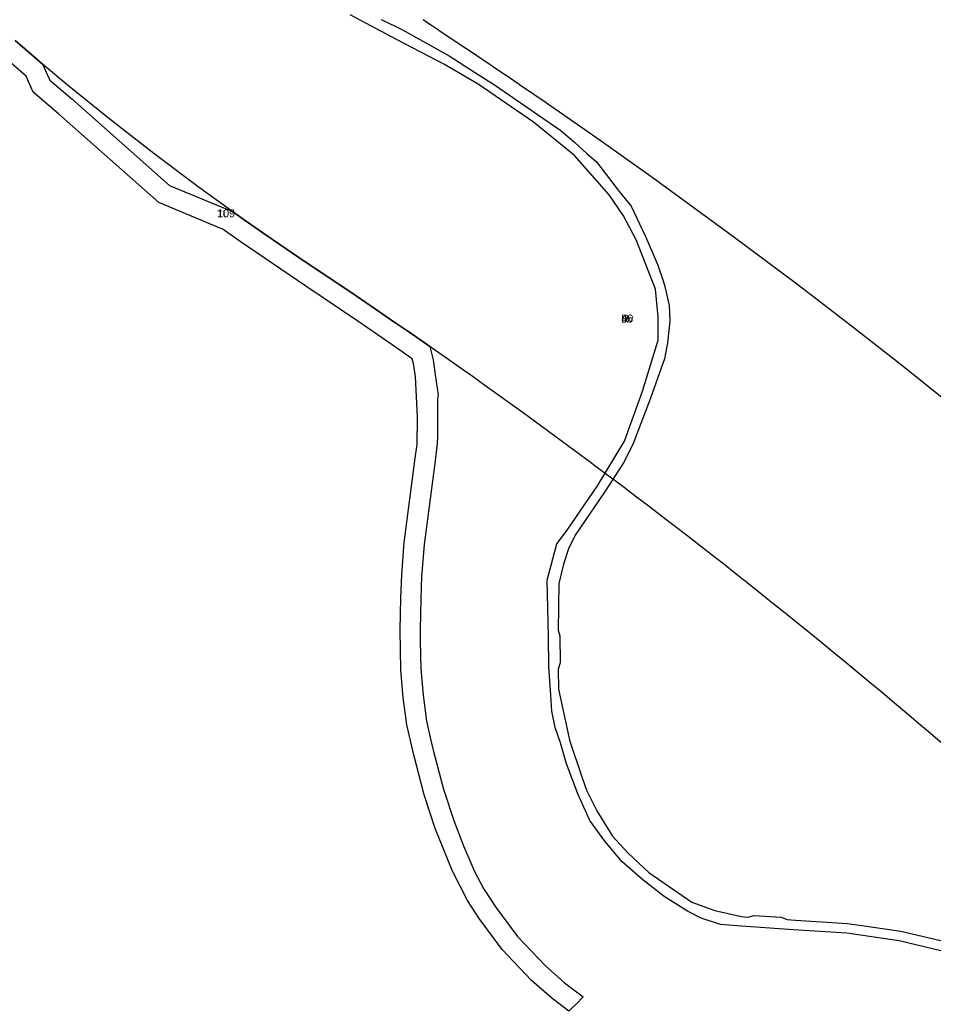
# Model space of a CAD drawing. Extents: x -545758 to -541641, y -1153152 to -1149975.
# Drawn here: x -543035 to -542350, y -1151306 to -1150563 of the extents above; entities that cross this region are included whole.
import ezdxf

# ---------------------------------------------------------------- set-up
doc = ezdxf.new("R2010")
doc.units = 0
for name, color, linetype in [('90310013', 7, 'Continuous'), ('90350033', 7, 'Continuous'), ('90380023', 7, 'Continuous'), ('ID_navrh', 7, 'Continuous'), ('ID_rezerva', 7, 'Continuous'), ('ID_rezervaR', 7, 'Continuous')]:
    doc.layers.add(name, color=color, linetype=linetype)

msp = doc.modelspace()

# ---------------------------------------------------------------- linework, layer by layer
at = {"layer": '90310013'}
for points in [[(-542336.56, -1151262.44), (-542375.15, -1151253.34), (-542414.44, -1151247.65), (-542454.35, -1151245.05), (-542493.4, -1151242.2), (-542509.26, -1151240.97), (-542523.59, -1151236.28), (-542533.99, -1151231.03), (-542551.48, -1151219.99), (-542567.35, -1151207.59), (-542582.93, -1151194.04), (-542595.99, -1151178.55), (-542607.01, -1151163.11), (-542616.12, -1151143.06), (-542624.64, -1151120.51), (-542629.05, -1151104.9), (-542633.03, -1151093.29), (-542635.51, -1151081.03), (-542636.43, -1151069), (-542637.98, -1151047.59), (-542638.05, -1151024.8), (-542639.22, -1150982.71), (-542631.93, -1150955.49), (-542624.02, -1150945.26), (-542601.49, -1150912.16), (-542581.09, -1150878.47), (-542567.63, -1150840.97), (-542555.97, -1150802.94), (-542555.82, -1150785.27), (-542558.01, -1150764.47), (-542572.32, -1150727.63), (-542581.97, -1150709.69), (-542592.51, -1150693.89), (-542618.67, -1150664.43), (-542649.47, -1150639.4), (-542690.78, -1150610.95), (-542716.17, -1150596.02), (-542751.54, -1150577.56), (-542786.83, -1150558.73)], [(-542763.51, -1150562.3), (-542752.7, -1150567.55), (-542747.63, -1150570.02), (-542712.51, -1150589.48), (-542693.55, -1150601.76), (-542678.6, -1150611.44), (-542645.66, -1150634.13), (-542628.79, -1150645.63), (-542618.41, -1150654.69), (-542609.26, -1150662.77), (-542602.24, -1150669.02), (-542586.51, -1150689.38), (-542585.01, -1150691.28), (-542576.23, -1150702.32), (-542565.68, -1150724.59), (-542565.25, -1150725.57), (-542556.14, -1150746.63), (-542552.24, -1150758.4), (-542550.87, -1150762.55), (-542547.73, -1150776.78), (-542547.18, -1150788.22), (-542547.89, -1150795.48), (-542548.81, -1150804.8), (-542551.16, -1150816.8), (-542557.56, -1150834.96), (-542561.62, -1150846.28), (-542574.79, -1150881.02), (-542581.96, -1150894.8), (-542595.71, -1150916.11), (-542618.19, -1150949.13), (-542623.17, -1150959.34), (-542626.89, -1150970.85), (-542630.5, -1150985.34), (-542630.99, -1151020.31), (-542629.55, -1151024.45), (-542629.35, -1151044.93), (-542630.81, -1151049.59), (-542630.67, -1151064.57), (-542623.4, -1151098.08), (-542622.37, -1151102.81), (-542612.76, -1151131.18), (-542609.63, -1151140.42), (-542601.81, -1151155.76), (-542590.02, -1151174.76), (-542578.28, -1151187.68), (-542562.98, -1151202.13), (-542530.65, -1151224.32), (-542513.28, -1151230.63), (-542493.28, -1151235.11), (-542491.06, -1151235.26), (-542488.5, -1151235.44), (-542484.13, -1151234.29), (-542463.53, -1151235.63), (-542459.17, -1151237.41), (-542452.78, -1151237.84), (-542413.96, -1151240.37), (-542404.95, -1151241.63), (-542373.91, -1151245.95), (-542362.09, -1151248.73), (-542334.58, -1151255.2)]]:
    msp.add_lwpolyline(points, dxfattribs=at)
at = {"layer": '90350033'}
for points in [[(-542732.169, -1150562.29), (-542728.606, -1150564.721), (-542725.026, -1150567.153), (-542721.454, -1150569.568), (-542717.877, -1150571.975), (-542714.287, -1150574.378), (-542700.62, -1150583.483), (-542700.508, -1150583.558), (-542700.422, -1150583.616), (-542690.459, -1150590.288), (-542690.252, -1150590.427), (-542680.304, -1150597.125), (-542680.108, -1150597.257), (-542670.175, -1150603.979), (-542669.984, -1150604.109), (-542660.065, -1150610.854), (-542659.86, -1150610.994), (-542649.958, -1150617.765), (-542649.761, -1150617.899), (-542639.872, -1150624.695), (-542639.669, -1150624.836), (-542629.796, -1150631.657), (-542599.485, -1150652.81), (-542559.547, -1150681.187), (-542500.131, -1150724.486), (-542451.266, -1150761.091), (-542412.138, -1150791.071), (-542373.481, -1150821.284), (-542335.295, -1150851.725)], [(-542342.761, -1151105.549), (-542351.717, -1151097.883), (-542360.69, -1151090.241), (-542369.686, -1151082.618), (-542378.701, -1151075.013), (-542387.729, -1151067.435), (-542396.777, -1151059.879), (-542405.844, -1151052.342), (-542414.931, -1151044.827), (-542424.031, -1151037.336), (-542433.153, -1151029.866), (-542442.292, -1151022.417), (-542451.446, -1151014.993), (-542460.62, -1151007.589), (-542469.812, -1151000.207), (-542479.02, -1150992.848), (-542488.243, -1150985.514), (-542497.486, -1150978.201), (-542506.749, -1150970.907), (-542516.026, -1150963.639), (-542525.318, -1150956.394), (-542534.628, -1150949.172), (-542543.958, -1150941.971), (-542553.302, -1150934.794), (-542562.662, -1150927.64), (-542572.039, -1150920.509), (-542581.435, -1150913.4), (-542590.844, -1150906.315), (-542600.27, -1150899.254), (-542609.714, -1150892.215), (-542619.175, -1150885.198), (-542628.65, -1150878.206), (-542638.14, -1150871.238), (-542647.647, -1150864.292), (-542657.168, -1150857.372), (-542666.707, -1150850.474), (-542676.264, -1150843.597), (-542685.833, -1150836.746), (-542695.418, -1150829.919), (-542705.017, -1150823.116), (-542714.633, -1150816.337), (-542724.263, -1150809.581), (-542727.122, -1150807.586), (-542733.911, -1150802.849), (-542743.575, -1150796.138), (-542753.25, -1150789.455), (-542782.363, -1150769.55), (-542825.268, -1150740.761), (-542849.156, -1150724.571), (-542864.645, -1150713.816), (-542868.745, -1150710.935), (-542872.654, -1150708.173), (-542876.601, -1150705.37), (-542899.784, -1150688.636), (-542934.22, -1150662.874), (-542968.151, -1150636.389), (-542997.86, -1150612.258), (-543017.596, -1150595.722), (-543023.498, -1150590.698), (-543037.995, -1150578.194)]]:
    msp.add_lwpolyline(points, dxfattribs=at)
at = {"layer": '90380023'}
msp.add_lwpolyline([(-543037.995, -1150578.194), (-543023.498, -1150590.698), (-543017.596, -1150595.722), (-543012.19, -1150607.72), (-542995.69, -1150621.83), (-542922.39, -1150686.8), (-542879.33, -1150704.7), (-542876.817, -1150705.217), (-542872.654, -1150708.173), (-542868.745, -1150710.935), (-542864.645, -1150713.816), (-542849.156, -1150724.571), (-542825.268, -1150740.761), (-542782.363, -1150769.55), (-542753.25, -1150789.455), (-542743.575, -1150796.138), (-542733.911, -1150802.849), (-542727.122, -1150807.586), (-542724.58, -1150817.54), (-542723.025, -1150828.79), (-542720.95, -1150843.81), (-542721.4, -1150846.72), (-542721.41, -1150853.81), (-542721.43, -1150860.66), (-542721.46, -1150874.27), (-542721.713, -1150881.186), (-542721.75, -1150882.21), (-542723.19, -1150893.25), (-542731.37, -1150956.16), (-542733.04, -1150977.32), (-542733.27, -1150979.77), (-542733.99, -1150996.89), (-542734.48, -1151020.04), (-542734.3, -1151028.54), (-542733.87, -1151049.36), (-542732.15, -1151069.03), (-542729.5, -1151088.58), (-542726.76, -1151100.72), (-542724.61, -1151110.24), (-542716.97, -1151139.53), (-542708.99, -1151163.91), (-542701.98, -1151181.96), (-542696.44, -1151194.85), (-542693.68, -1151201.29), (-542686.54, -1151214.47), (-542685.84, -1151215.55), (-542677.84, -1151227.91), (-542661.27, -1151250.07), (-542640.42, -1151272.17), (-542626.16, -1151284.79), (-542612.07, -1151295.42), (-542614.61, -1151297.92), (-542614.96, -1151298.26), (-542622.881, -1151306.054), (-542635.662, -1151296.411), (-542650.867, -1151282.955), (-542672.769, -1151259.74), (-542690.157, -1151236.486), (-542698.845, -1151223.063), (-542710.092, -1151201.1), (-542723.085, -1151169.068), (-542731.368, -1151143.76), (-542739.187, -1151113.786), (-542744.276, -1151091.244), (-542747.062, -1151070.692), (-542748.856, -1151050.17), (-542749.483, -1151020.037), (-542748.983, -1150996.416), (-542748.245, -1150978.853), (-542746.292, -1150954.59), (-542738.064, -1150891.313), (-542736.735, -1150881.125), (-542736.435, -1150860.924), (-542736.97, -1150850.244), (-542737.974, -1150830.194), (-542739.323, -1150820.432), (-542740.273, -1150816.714), (-542752.108, -1150808.475), (-542781.085, -1150788.56), (-542820.014, -1150762.285), (-542869.289, -1150728.873), (-542882.77, -1150719.307), (-542883.759, -1150719.103), (-542930.463, -1150699.688), (-543005.54, -1150633.143), (-543024.488, -1150616.94), (-543029.924, -1150604.876), (-543054.91, -1150583.328)], dxfattribs=at)

# ---------------------------------------------------------------- texts
at = {"layer": '90350033'}
msp.add_text('DV', height=5, rotation=360, dxfattribs=at).set_placement((-542583.553, -1150789.597))
at = {"layer": '90380023'}
msp.add_text('TU', height=5, rotation=0, dxfattribs=at).set_placement((-542886.558, -1150710.683))
at = {"layer": 'ID_navrh'}
msp.add_text('109', height=6, rotation=0, dxfattribs=at).set_placement((-542886.558, -1150710.683))
at = {"layer": 'ID_rezerva'}
msp.add_text('46', height=6, rotation=0, dxfattribs=at).set_placement((-542583.553, -1150789.597))
at = {"layer": 'ID_rezervaR'}
msp.add_text('R', height=6, rotation=0, dxfattribs=at).set_placement((-542583.553, -1150789.597))

doc.saveas('drawing.dxf')
